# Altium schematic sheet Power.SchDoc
size A4; Revision: B.2
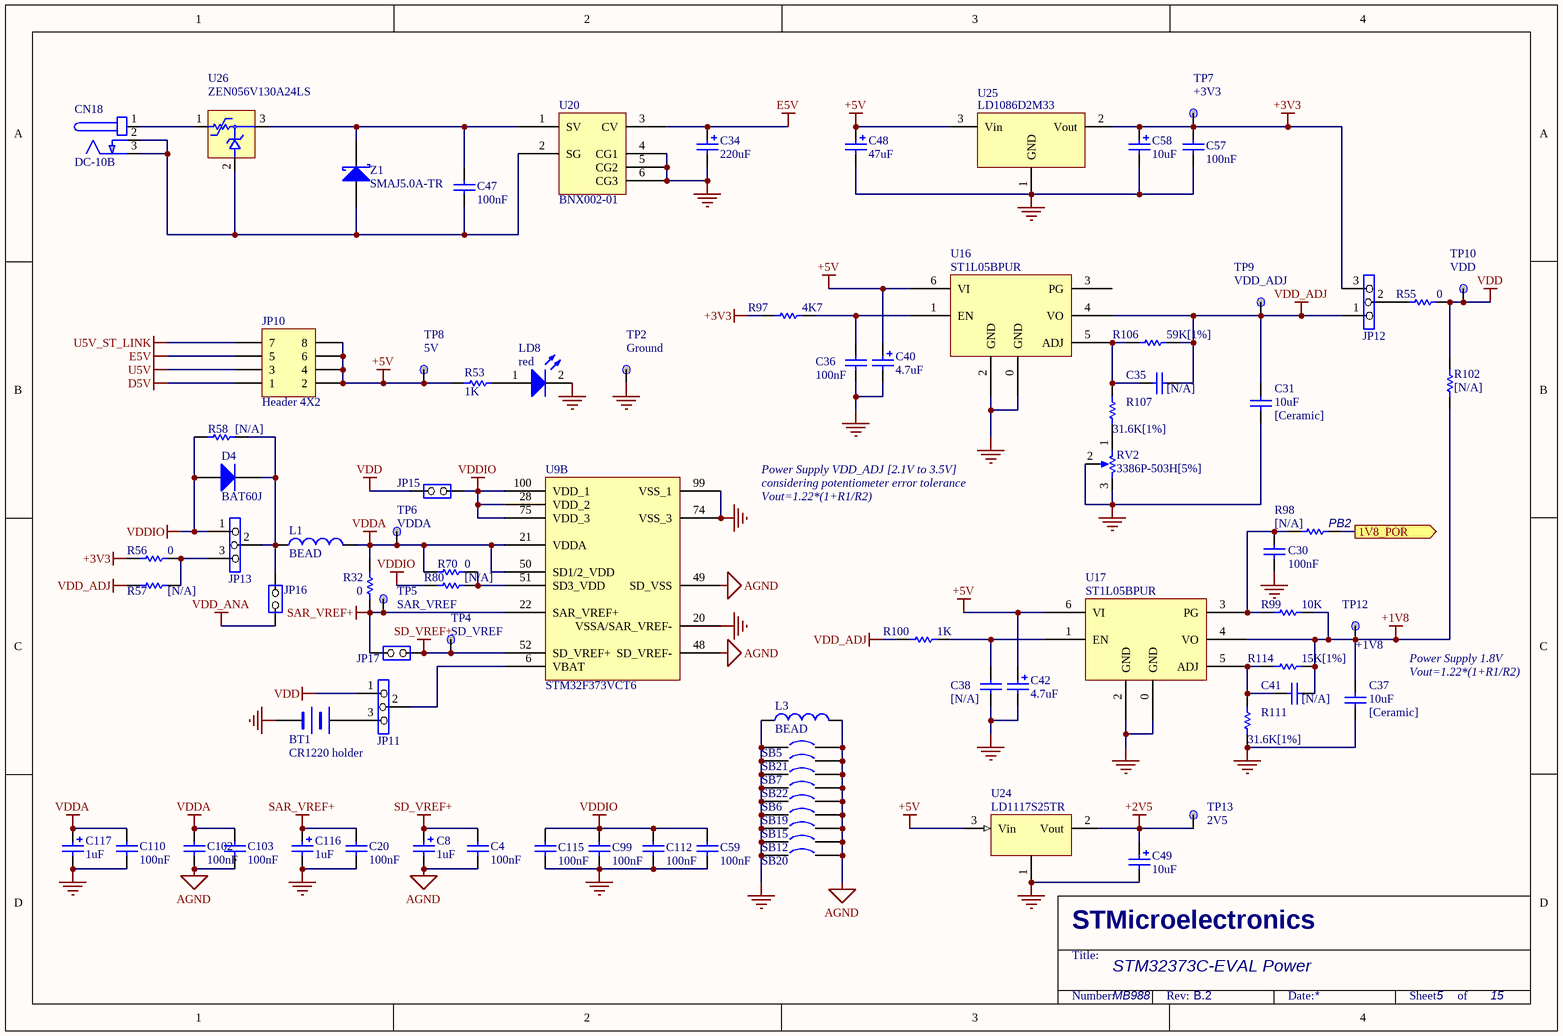
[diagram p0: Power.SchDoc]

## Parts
BT1  CR1220 holder  [LI1220_1]
C4  100nF  [0603C]
C8  1uF  [TAN-A]
C20  100nF  [0603C]
C30  100nF  [0603C]
C31  10uF  [0805C]
C34  220uF  [C310M]
C35  [N/A]  [0603C]
C36  100nF  [0603C]
C37  10uF  [0805C]
C38  [N/A]  [0603C]
C40  4.7uF  [TAN-A]
C41  [N/A]  [0603C]
C42  4.7uF  [TAN-A]
C47  100nF  [0603C]
C48  47uF  [C200M]
C49  10uF  [TAN-A]
C57  100nF  [0603C]
C58  10uF  [TAN-A]
C59  100nF  [0603C]
C99  100nF  [0603C]
C102  100nF  [0603C]
C103  100nF  [0603C]
C110  100nF  [0603C]
C112  100nF  [0603C]
C115  100nF  [0603C]
C116  1uF  [TAN-A]
C117  1uF  [TAN-A]
CN18  DC-10B  [DC10B]
D4  BAT60J  [SOD-323]
JP10  Header 4X2  [2*4P]
JP11  (no value)  [SIP3]
JP12  (no value)  [SIP3]
JP13  (no value)  [SIP3]
JP15  (no value)  [SIP2]
JP16  (no value)  [SIP2]
JP17  (no value)  [SIP2]
L1  BEAD  [0603L]
L3  BEAD  [0603L]
LD8  red  [0603D]
R32  0  [0603R]
R53  1K  [0603R]
R55  0  [0603R]
R56  0  [0603R]
R57  [N/A]  [0603R]
R58  [N/A]  [0603R]
R70  0  [0603R]
R80  [N/A]  [0603R]
R97  4K7  [0603R]
R98  [N/A]  [0603R]
R99  10K  [0603R]
R100  1K  [0603R]
R102  [N/A]  [0603R]
R106  59K[1%]  [0603R]
R107  31.6K[1%]  [0603R]
R111  31.6K[1%]  [0603R]
R114  15K[1%]  [0603R]
RV2  3386P-503H[5%]  [3296W]
SB5  (no value)  [JP2_SMD]
SB6  (no value)  [JP2_SMD]
SB7  (no value)  [JP2_SMD]
SB12  (no value)  [JP2_SMD]
SB15  (no value)  [JP2_SMD]
SB19  (no value)  [JP2_SMD]
SB20  (no value)  [JP2_SMD]
SB21  (no value)  [JP2_SMD]
SB22  (no value)  [JP2_SMD]
TP2  Ground  [TP]
TP4  SD_VREF  [TP]
TP5  SAR_VREF  [TP]
TP6  VDDA  [TP]
TP7  +3V3  [TP]
TP8  5V  [TP]
TP9  VDD_ADJ  [TP]
TP10  VDD  [TP]
TP12  +1V8  [TP]
TP13  2V5  [TP]
U9  STM32F373VCT6  [IC149-100-025-B5]  (part B of 2)
U16  ST1L05BPUR  [DFN6(3X3)]
U17  ST1L05BPUR  [DFN6(3X3)]
U20  BNX002-01  [BNX001]
U24  LD1117S25TR  [SOT-223]
U25  LD1086D2M33  [D2PAK/A]
U26  ZEN056V130A24LS  [polyzen]
Z1  SMAJ5.0A-TR  [1R1C]

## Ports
1V8_POR (out)

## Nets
+1V8: C37.1 C41.2 R99.2 R102.2 R114.1 TP12.1 U17.4(VO)
+2V5: C49.1 TP13.1 U24.2(Vout)
+3V3: C57.1 C58.1 JP12.3 R56.2 R97.2 TP7.1 U25.2(Vout)
+5V: C40.1 C42.1 C48.1 JP10.2 JP10.4 JP10.6 JP10.8 R53.2 TP8.1 U16.6(VI) U17.6(VI) U24.3(Vin) U25.3(Vin)
AGND: C4.1 C8.2 C102.1 C103.1 L3.2 SB5.2 SB6.2 SB7.2 SB12.2 SB15.2 SB19.2 SB20.2 SB21.2 SB22.2 U9.48(SD_VREF-) U9.49(SD_VSS)
D5V: JP10.1
E5V: C34.1 JP10.5 U20.3(CV)
GND: BT1.2(-) C20.1 C30.2 C31.2 C34.2 C36.2 C37.2 C38.2 C40.2 C42.2 C48.2 C49.2 C57.2 C58.2 C59.2 C99.2 C110.1 C112.2 C115.2 C116.2 C117.2 L3.1 LD8.2(K) R111.2 RV2.2(TAP) RV2.3(TOP) SB5.1 SB6.1 SB7.1 SB12.1 SB15.1 SB19.1 SB20.1 SB21.1 SB22.1 TP2.1 U9.20(VSSA/SAR_VREF-) U9.74(VSS_3) U9.99(VSS_1) U16.0(GND) U16.2(GND) U17.0(GND) U17.2(GND) U20.4(CG1) U20.5(CG2) U20.6(CG3) U24.1 U25.1(GND)
SAR_VREF+: C20.2 C116.1 JP17.2(NO) R32.2 TP5.1 U9.22(SAR_VREF+)
SD_VREF+: C4.2 C8.1 JP17.1(COMMON) TP4.1 U9.52(SD_VREF+)
U5V: JP10.3
U5V_ST_LINK: JP10.7
VDD: JP11.1 JP15.2(NO) R55.1 R102.1 TP10.1
VDD_ADJ: C31.1 C35.2 JP12.1 R57.2 R100.2 R106.1 TP9.1 U16.4(VO)
VDD_ANA: JP16.1(COMMON)
VDDA: C102.2 C103.2 C110.2 C117.1 L1.2 R32.1 R70.1 TP6.1 U9.21(VDDA) U9.50(SD1/2_VDD)
VDDIO: C59.1 C99.1 C112.1 C115.1 D4.1(A) JP13.1 JP15.1(COMMON) R58.1 R80.1 U9.28(VDD_2) U9.75(VDD_3) U9.100(VDD_1)
1V8_POR: R98.1 ; port 1V8_POR
NetBT1_1: BT1.1(+) JP11.3
NetC30_1: C30.1 R98.2 R99.1 U17.3(PG)
NetC35_1: C35.1 R106.2 R107.1 U16.5(ADJ)
NetC36_1: C36.1 R97.1 U16.1(EN)
NetC38_1: C38.1 R100.1 U17.1(EN)
NetC41_1: C41.1 R111.1 R114.2 U17.5(ADJ)
NetC47_1: C47.1 U20.1(SV) U26.3 Z1.2(K)
NetC47_2: C47.2 CN18.2(GND) CN18.3(GND) U20.2(SG) U26.2 Z1.1(A)
NetCN18_1: CN18.1(+) U26.1
NetD4_2: D4.2(K) JP13.2 JP16.2(NO) L1.1 R58.2
NetJP11_2: JP11.2 U9.6(VBAT)
NetJP12_2: JP12.2 R55.2
NetJP13_3: JP13.3 R56.1 R57.1
NetLD8_1: LD8.1(A) R53.1
NetR70_2: R70.2 R80.2 U9.51(SD3_VDD)
NetR107_2: R107.2 RV2.1(BOT)

Not connected (* = marked no-connect by the designer): U16 3(PG)

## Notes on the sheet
- (near C31) [Ceramic]
- Power Supply VDD_ADJ [2.1V to 3.5V]
- Vout=1.22*(1+R1/R2)
- considering potentiometer error tolerance
- (near R98) PB2
- (near C37) [Ceramic]
- Power Supply 1.8V
- STM32373C-EVAL Power
- MB988
- 5
- 15

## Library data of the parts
BT1 = BATTERY
C4 C20 C30 C31 C35-C38 C41 C57 C102 C103 C110 = Cap: Capacitor; Value: 10nF
C8 C48 C116 C117 = Cap Pol1: Polarized Capacitor (Radial); Value: 10uF
C34 = Cap Pol1: Polarized Capacitor (Radial); Value: 47uF
C40 C42 = Cap Pol1: Polarized Capacitor (Radial); Value: 100pF
C47 = CAP: Capacitor; Value: 100pF
C49 C58 = Cap Pol1: Polarized Capacitor (Radial)
C59 C99 C112 C115 = CAP: Capacitor
CN18 = PJ202A
D4 = Diode: Default Diode; Code - JEDEC: DO-214-AB
JP10 = Header 4X2: Header, 4-Pin, Dual row
JP11-JP13 = Jumper3
JP15-JP17 = JP2
L1 L3 = Inductor: Value: 100uH
LD8 = LED2: Typical RED, GREEN, YELLOW, AMBER GaAs LED
R32 R55-R58 R70 R80 R98 R102 R106 R107 R111 R114 = Res1: Resistor; Value: 1K
R53 R100 = res1: Resistor
R97 R99 = res1: Resistor; Value: 1K
RV2 = RV
SB5-SB7 SB12 SB15 SB19-SB22 = Circuit Breaker
TP2 TP4-TP10 TP12 TP13 = TP
U9 = Goldfish
U16 U17 = ST1L05
U20 = BNX002
U24 = LD1117
U25 = VOLTREG1
Z1 = D Schottky: Schottky Diode; Code - JEDEC: DO-214-AA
